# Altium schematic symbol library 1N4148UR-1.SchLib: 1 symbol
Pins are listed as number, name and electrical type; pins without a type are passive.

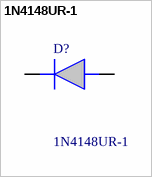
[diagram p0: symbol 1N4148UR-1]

## 1N4148UR-1
designator D?
Diodes - General Purpose, Power, Switching Switching; Manufacturer_Name: Microsemi Corporation; Geometry.Height: 1.7mm
footprint 1N4148UR1
pins: 1 K, 2 A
